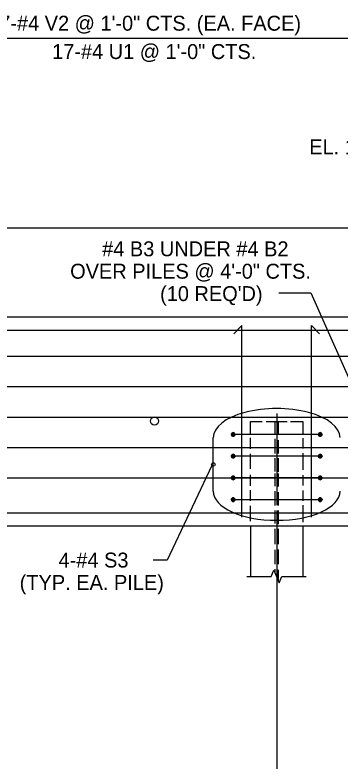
# Model space of a CAD drawing. Extents: x -41 to 191, y -168 to 6.
# Drawn here: x 154.55 to 160.78, y -40.75 to -26.46 of the extents above; entities that cross this region are included whole.
import ezdxf

# ---------------------------------------------------------------- set-up
doc = ezdxf.new("R2010")
doc.units = 0
for name, color, linetype in [('Dimension Lines', 7, 'Continuous'), ('Dimension Lines CELL', 7, 'Continuous'), ('Mis Object Lines', 7, 'Continuous'), ('Rebar Lines', 7, 'Continuous'), ('Rebar Lines CELL', 7, 'Continuous'), ('Text', 7, 'Continuous')]:
    doc.layers.add(name, color=color, linetype=linetype)

msp = doc.modelspace()

# ---------------------------------------------------------------- linework, layer by layer
at = {"layer": 'Dimension Lines'}
for p, q in [((148.448, -26.909), (164.521, -26.909)), ((149.531, -26.909), (164.551, -26.909)), ((159.608, -31.784), (160.22, -31.784)), ((160.22, -31.784), (161.225, -34.049)), ((158.352, -35.588), (158.352, -34.56)), ((158.325, -35.097), (157.466, -36.908)), ((159.566, -36.249), (159.566, -42.873)), ((157.466, -36.908), (157.199, -36.908))]:
    msp.add_line(p, q, dxfattribs=at)
for centre, start_param, end_param in [((159.566, -34.56), 0, 3.141593), ((159.566, -35.588), 3.141593, 6.283185)]:
    msp.add_ellipse(centre, major_axis=(1.215, 0), ratio=0.457627, start_param=start_param, end_param=end_param, dxfattribs=at)
at = {"layer": 'Dimension Lines CELL'}
msp.add_circle((158.352, -35.074), 0.0353, dxfattribs=at)
at = {"layer": 'Mis Object Lines'}
for p, q in [((137.623, -30.54), (164.491, -30.54)), ((147.948, -32.249), (168.185, -32.249)), ((133.764, -36.249), (168.185, -36.249))]:
    msp.add_line(p, q, dxfattribs=at)
at = {"layer": 'Rebar Lines'}
for p, q in [((158.9, -32.415), (158.746, -32.569)), ((158.9, -36.082), (158.9, -32.415)), ((160.233, -32.415), (160.387, -32.569)), ((160.233, -36.082), (160.233, -32.415)), ((127.69, -32.5), (166.732, -32.5)), ((149.253, -32.999), (167.24, -32.999)), ((149.253, -33.582), (167.24, -33.582)), ((159.566, -34.097), (159.566, -35.854)), ((149.253, -34.165), (167.24, -34.165)), ((159.535, -34.491), (159.535, -34.249)), ((159.598, -34.497), (159.598, -34.249)), ((159.535, -34.863), (159.535, -34.584)), ((159.598, -34.863), (159.598, -34.607)), ((149.253, -34.749), (167.24, -34.749)), ((159.535, -35.206), (159.535, -34.956)), ((159.598, -35.217), (159.598, -34.956)), ((159.535, -35.491), (159.535, -35.249)), ((159.598, -35.497), (159.598, -35.249)), ((149.253, -35.332), (167.24, -35.332)), ((159.535, -35.863), (159.535, -35.584)), ((159.598, -35.863), (159.598, -35.607)), ((127.69, -35.999), (166.825, -35.999)), ((159.535, -36.206), (159.535, -35.956)), ((159.566, -35.958), (159.566, -36.249)), ((159.598, -36.217), (159.598, -35.956)), ((159.066, -36.266), (159.066, -37.218)), ((160.067, -36.266), (160.067, -37.218)), ((159.535, -36.601), (159.535, -36.304)), ((159.566, -36.318), (159.566, -37.524)), ((159.598, -36.601), (159.598, -36.31)), ((159.535, -36.984), (159.535, -36.711)), ((159.598, -36.984), (159.598, -36.705)), ((159.535, -37.152), (159.535, -37.077)), ((159.598, -37.301), (159.598, -37.089))]:
    msp.add_line(p, q, dxfattribs=at)
for points in [[(159.066, -34.482), (159.066, -34.249), (159.289, -34.249)], [(159.364, -34.249), (159.764, -34.249)], [(159.833, -34.249), (160.066, -34.249), (160.066, -34.495)], [(159.066, -34.773), (159.066, -34.565)], [(160.066, -34.571), (160.066, -34.77)], [(159.066, -35.16), (159.066, -34.868)], [(160.066, -34.855), (160.066, -35.176)], [(159.066, -35.482), (159.066, -35.274)], [(160.066, -35.28), (160.066, -35.479)], [(159.066, -35.773), (159.066, -35.565)], [(160.066, -35.571), (160.066, -35.77)], [(159.066, -36.16), (159.066, -35.868)], [(160.066, -35.855), (160.066, -36.176)], [(158.996, -37.218), (159.458, -37.218), (159.513, -37.098), (159.615, -37.343), (159.667, -37.218), (160.133, -37.218)]]:
    msp.add_lwpolyline(points, dxfattribs=at)
at = {"layer": 'Rebar Lines CELL'}
for p, q in [((160.4, -34.499), (158.733, -34.499)), ((160.4, -34.915), (158.733, -34.915)), ((160.4, -35.332), (158.733, -35.332)), ((160.4, -35.749), (158.733, -35.749))]:
    msp.add_line(p, q, dxfattribs=at)
for points in [[(158.733, -34.463), (158.72, -34.466), (158.708, -34.474), (158.7, -34.485), (158.698, -34.499), (158.7, -34.512), (158.708, -34.523), (158.72, -34.531), (158.733, -34.534), (158.746, -34.531), (158.758, -34.523), (158.766, -34.512), (158.768, -34.499), (158.766, -34.485), (158.758, -34.474), (158.747, -34.466), (158.733, -34.463), (158.733, -34.499), (158.733, -34.534), (158.72, -34.531), (158.733, -34.499), (158.708, -34.523), (158.7, -34.512), (158.733, -34.499), (158.698, -34.499), (158.7, -34.485), (158.733, -34.499), (158.708, -34.474), (158.72, -34.466), (158.733, -34.499), (158.747, -34.466), (158.758, -34.474), (158.733, -34.499), (158.766, -34.485), (158.768, -34.499), (158.733, -34.499), (158.766, -34.512), (158.758, -34.523), (158.733, -34.499), (158.746, -34.531)], [(160.4, -34.463), (160.386, -34.466), (160.375, -34.474), (160.367, -34.485), (160.365, -34.499), (160.367, -34.512), (160.375, -34.523), (160.386, -34.531), (160.4, -34.534), (160.413, -34.531), (160.425, -34.523), (160.432, -34.512), (160.435, -34.499), (160.432, -34.485), (160.425, -34.474), (160.413, -34.466), (160.4, -34.463), (160.4, -34.499), (160.4, -34.534), (160.386, -34.531), (160.4, -34.499), (160.375, -34.523), (160.367, -34.512), (160.4, -34.499), (160.365, -34.499), (160.367, -34.485), (160.4, -34.499), (160.375, -34.474), (160.386, -34.466), (160.4, -34.499), (160.413, -34.466), (160.425, -34.474), (160.4, -34.499), (160.432, -34.485), (160.435, -34.499), (160.4, -34.499), (160.432, -34.512), (160.425, -34.523), (160.4, -34.499), (160.413, -34.531)], [(158.733, -34.88), (158.72, -34.883), (158.708, -34.89), (158.7, -34.902), (158.698, -34.915), (158.7, -34.929), (158.708, -34.94), (158.72, -34.948), (158.733, -34.95), (158.746, -34.948), (158.758, -34.94), (158.766, -34.929), (158.768, -34.915), (158.766, -34.902), (158.758, -34.89), (158.747, -34.883), (158.733, -34.88), (158.733, -34.915), (158.733, -34.95), (158.72, -34.948), (158.733, -34.915), (158.708, -34.94), (158.7, -34.929), (158.733, -34.915), (158.698, -34.915), (158.7, -34.902), (158.733, -34.915), (158.708, -34.89), (158.72, -34.883), (158.733, -34.915), (158.747, -34.883), (158.758, -34.89), (158.733, -34.915), (158.766, -34.902), (158.768, -34.915), (158.733, -34.915), (158.766, -34.929), (158.758, -34.94), (158.733, -34.915), (158.746, -34.948)], [(160.4, -34.88), (160.386, -34.883), (160.375, -34.89), (160.367, -34.902), (160.365, -34.915), (160.367, -34.929), (160.375, -34.94), (160.386, -34.948), (160.4, -34.95), (160.413, -34.948), (160.425, -34.94), (160.432, -34.929), (160.435, -34.915), (160.432, -34.902), (160.425, -34.89), (160.413, -34.883), (160.4, -34.88), (160.4, -34.915), (160.4, -34.95), (160.386, -34.948), (160.4, -34.915), (160.375, -34.94), (160.367, -34.929), (160.4, -34.915), (160.365, -34.915), (160.367, -34.902), (160.4, -34.915), (160.375, -34.89), (160.386, -34.883), (160.4, -34.915), (160.413, -34.883), (160.425, -34.89), (160.4, -34.915), (160.432, -34.902), (160.435, -34.915), (160.4, -34.915), (160.432, -34.929), (160.425, -34.94), (160.4, -34.915), (160.413, -34.948)], [(158.733, -35.297), (158.72, -35.299), (158.708, -35.307), (158.7, -35.318), (158.698, -35.332), (158.7, -35.345), (158.708, -35.357), (158.72, -35.364), (158.733, -35.367), (158.746, -35.364), (158.758, -35.357), (158.766, -35.345), (158.768, -35.332), (158.766, -35.318), (158.758, -35.307), (158.747, -35.299), (158.733, -35.297), (158.733, -35.332), (158.733, -35.367), (158.72, -35.364), (158.733, -35.332), (158.708, -35.357), (158.7, -35.345), (158.733, -35.332), (158.698, -35.332), (158.7, -35.318), (158.733, -35.332), (158.708, -35.307), (158.72, -35.299), (158.733, -35.332), (158.747, -35.299), (158.758, -35.307), (158.733, -35.332), (158.766, -35.318), (158.768, -35.332), (158.733, -35.332), (158.766, -35.345), (158.758, -35.357), (158.733, -35.332), (158.746, -35.364)], [(160.4, -35.297), (160.386, -35.299), (160.375, -35.307), (160.367, -35.318), (160.365, -35.332), (160.367, -35.345), (160.375, -35.357), (160.386, -35.364), (160.4, -35.367), (160.413, -35.364), (160.425, -35.357), (160.432, -35.345), (160.435, -35.332), (160.432, -35.318), (160.425, -35.307), (160.413, -35.299), (160.4, -35.297), (160.4, -35.332), (160.4, -35.367), (160.386, -35.364), (160.4, -35.332), (160.375, -35.357), (160.367, -35.345), (160.4, -35.332), (160.365, -35.332), (160.367, -35.318), (160.4, -35.332), (160.375, -35.307), (160.386, -35.299), (160.4, -35.332), (160.413, -35.299), (160.425, -35.307), (160.4, -35.332), (160.432, -35.318), (160.435, -35.332), (160.4, -35.332), (160.432, -35.345), (160.425, -35.357), (160.4, -35.332), (160.413, -35.364)], [(158.733, -35.713), (158.72, -35.716), (158.708, -35.724), (158.7, -35.735), (158.698, -35.749), (158.7, -35.762), (158.708, -35.773), (158.72, -35.781), (158.733, -35.784), (158.746, -35.781), (158.758, -35.773), (158.766, -35.762), (158.768, -35.749), (158.766, -35.735), (158.758, -35.724), (158.747, -35.716), (158.733, -35.713), (158.733, -35.749), (158.733, -35.784), (158.72, -35.781), (158.733, -35.749), (158.708, -35.773), (158.7, -35.762), (158.733, -35.749), (158.698, -35.749), (158.7, -35.735), (158.733, -35.749), (158.708, -35.724), (158.72, -35.716), (158.733, -35.749), (158.747, -35.716), (158.758, -35.724), (158.733, -35.749), (158.766, -35.735), (158.768, -35.749), (158.733, -35.749), (158.766, -35.762), (158.758, -35.773), (158.733, -35.749), (158.746, -35.781)], [(160.4, -35.713), (160.386, -35.716), (160.375, -35.724), (160.367, -35.735), (160.365, -35.749), (160.367, -35.762), (160.375, -35.773), (160.386, -35.781), (160.4, -35.784), (160.413, -35.781), (160.425, -35.773), (160.432, -35.762), (160.435, -35.749), (160.432, -35.735), (160.425, -35.724), (160.413, -35.716), (160.4, -35.713), (160.4, -35.749), (160.4, -35.784), (160.386, -35.781), (160.4, -35.749), (160.375, -35.773), (160.367, -35.762), (160.4, -35.749), (160.365, -35.749), (160.367, -35.735), (160.4, -35.749), (160.375, -35.724), (160.386, -35.716), (160.4, -35.749), (160.413, -35.716), (160.425, -35.724), (160.4, -35.749), (160.432, -35.735), (160.435, -35.749), (160.4, -35.749), (160.432, -35.762), (160.425, -35.773), (160.4, -35.749), (160.413, -35.781)]]:
    msp.add_lwpolyline(points, dxfattribs=at)
msp.add_circle((157.225, -34.242), 0.0773, dxfattribs=at)

# ---------------------------------------------------------------- texts
at = {"layer": 'Text'}
for s, p in [('17-#4 V2 @ 1\'-0" CTS. (EA. FACE)', (154.037, -26.766)), ('17-#4 U1 @ 1\'-0" CTS.', (155.263, -27.309)), ('EL. 182.07', (160.19, -29.133)), ('#4 B3 UNDER #4 B2', (156.222, -31.087)), ('OVER PILES @ 4\'-0" CTS.', (155.609, -31.516)), ("(10 REQ'D)", (157.332, -31.945)), ('4-#4 S3', (155.387, -37.048)), ('(TYP. EA. PILE)', (154.642, -37.477))]:
    msp.add_text(s, height=0.286, dxfattribs=at).set_placement(p)

doc.saveas('drawing.dxf')
